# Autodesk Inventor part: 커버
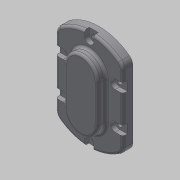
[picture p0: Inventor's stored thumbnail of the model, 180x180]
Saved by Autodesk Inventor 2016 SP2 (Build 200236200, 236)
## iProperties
Created: 2019-03
Part Number: 커버
Material: 알루미늄 6061
Document SubType Name: Modeling
Designer: mduedu
Density: 1 g/cm^3
Appearance: 기본값
Author: mduedu
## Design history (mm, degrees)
sketch "스케치1"
  geometry: L1 (44.721, -40)-(-44.721, -40); L2 (44.721, 40)-(-44.721, 40); A1 r 60 centre (0, 0) between (44.721, -40) and (44.721, 40); A2 r 60 centre (0, 0) between (-44.721, 40) and (-44.721, -40); 5 further points
  constraints: 6 point on circle, 4 end point, 2 centre point, 2 coincident, 2 horizontal alignment, 2 midpoint, 2 vertical alignment, 1 horizontal, 1 parallel
  dimensions: "d0" = 60 radius of A1; "d2" = 80 distance between parallel lines of L2 L1; "d3" = 120 distance of point (-60, 0) point (60, 0) (derived)
extrude "돌출1" new body sketch "스케치1" distance "d4" = 12; taper "d5" = 0 deg
sketch "스케치2"
  geometry: L1 (-20, -22)-(20, -22); L2 (20, -22)-(20, 22); L3 (20, 22)-(-20, 22); L4 (-20, 22)-(-20, -22); L5 (-20, -22)-(20, 22); L6 (20, -22)-(-20, 22); 3 further points
  constraints: 12 end point, 4 midpoint, 2 horizontal alignment, 2 parallel, 1 horizontal, 1 perpendicular, 4 other
  dimensions: "d6" = 40 distance between parallel lines of L2 L4; "d8" = 44 distance between parallel lines of L1 L3
extrude "돌출2" join sketch "스케치2" distance "d9" = 10; taper "d10" = 0 deg
fillet "모깎기1" dims "d11" = 10
fillet "모깎기2" dims "d12" = 3
sketch "스케치3"
  geometry: L1 (31, -22)-(31, 22); L2 (-31, 22)-(-31, -22); L3 (-31, -22)-(31, 22); L4 (31, -22)-(-31, 22); A1 r 31 centre (0, 22) between (31, 22) and (-31, 22); A2 r 31 centre (0, -22) between (-31, -22) and (31, -22); 7 further points
  constraints: 8 end point, 6 point on circle, 4 coincident, 3 tangent, 2 centre point, 2 midpoint, 1 parallel, 1 vertical, 1 vertical alignment
  dimensions: "d13" = 31 radius of A1; "d15" = 44 distance of A2.centre A1.centre
hole "구멍2" sketch "스케치3" at (-31, 22), (-31, -22), (31, -22), (31, 22), (0, 53), (0, -53) diameter "d28" = 5.5; stored, may be unused: countersink angle "d32" = 90 deg, drill point angle "d34" = 118 deg; dims "d29" = 6, "d30" = 4, "d31" = 2, "d33" = 8
sketch "스케치5"
  geometry: L1 (-40, 40)-(-40, -40) reference; L2 (40, -40)-(40, 40) reference; L3 (-5.5, 53)-(-5.5, 59.747); L4 (5.5, 53)-(5.5, 59.747); L5 (-31, 27.5)-(-40, 27.5); L6 (-31, 16.5)-(-40, 16.5); L7 (-31, -16.5)-(-40, -16.5); L8 (-31, -27.5)-(-40, -27.5); L9 (-5.5, -53)-(-5.5, -59.747); L10 (5.5, -53)-(5.5, -59.747); L11 (31, -27.5)-(40, -27.5); L12 (31, -16.5)-(40, -16.5); L13 (31, 16.5)-(40, 16.5); L14 (31, 27.5)-(40, 27.5); C1 r 2.75 at (0, 53) reference; C2 r 2.75 at (-31, 22) reference; C3 r 2.75 at (-31, -22) reference; C4 r 2.75 at (0, -53) reference; C5 r 2.75 at (31, -22) reference; C6 r 2.75 at (31, 22) reference; A1 r 60 centre (0, 0) between (36, 48) and (-36, 48) reference; A2 r 10 centre (-30, 40) between (-36, 48) and (-40, 40) reference; A3 r 10 centre (-30, -40) between (-40, -40) and (-36, -48) reference; A4 r 60 centre (0, 0) between (-36, -48) and (36, -48) reference; A5 r 10 centre (30, -40) between (36, -48) and (40, -40) reference; A6 r 10 centre (30, 40) between (40, 40) and (36, 48) reference; A7 r 5.5 centre (0, 53) between (-5.5, 53) and (5.5, 53); A8 r 5.5 centre (-31, 22) between (-31, 16.5) and (-31, 27.5); A9 r 5.5 centre (-31, -22) between (-31, -27.5) and (-31, -16.5); A10 r 5.5 centre (0, -53) between (5.5, -53) and (-5.5, -53); A11 r 5.5 centre (31, -22) between (31, -16.5) and (31, -27.5); A12 r 5.5 centre (31, 22) between (31, 27.5) and (31, 16.5); 1 further point
  constraints: 24 end point, 16 point on circle, 12 tangent, 8 parallel, 8 point on line, 6 centre point, 5 concentric, 4 horizontal, 1 coincident, 1 vertical
  dimensions: "d35" = 11 diameter of A7; "d36" = 11 diameter of A8; "d37" = 11 diameter of A9; "d38" = 11 diameter of A10; "d39" = 11 diameter of A11; "d40" = 11 diameter of A12
extrude "돌출4" cut sketch "스케치5" distance "d41" = 5.4; taper "d42" = 0 deg
sketch "스케치6"
  geometry: C1 r 12.5 at (0, 22); 1 further point
  constraints: 1 centre point, 1 vertical alignment
  dimensions: "d43" = 25 diameter of C1; "d45" = 22 distance of C1.centre point (0, 0)
extrude "돌출5" cut sketch "스케치6" distance "d47" = 15; taper "d48" = 0 deg
node "솔리드1"
mirror "대칭1"
